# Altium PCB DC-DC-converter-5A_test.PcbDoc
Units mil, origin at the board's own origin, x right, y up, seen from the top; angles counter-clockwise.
Board outline 1075 x 720 mil, 2 copper layers (Top Layer, Bottom Layer); 21 components, 11 nets, 49 pads, 44 vias.
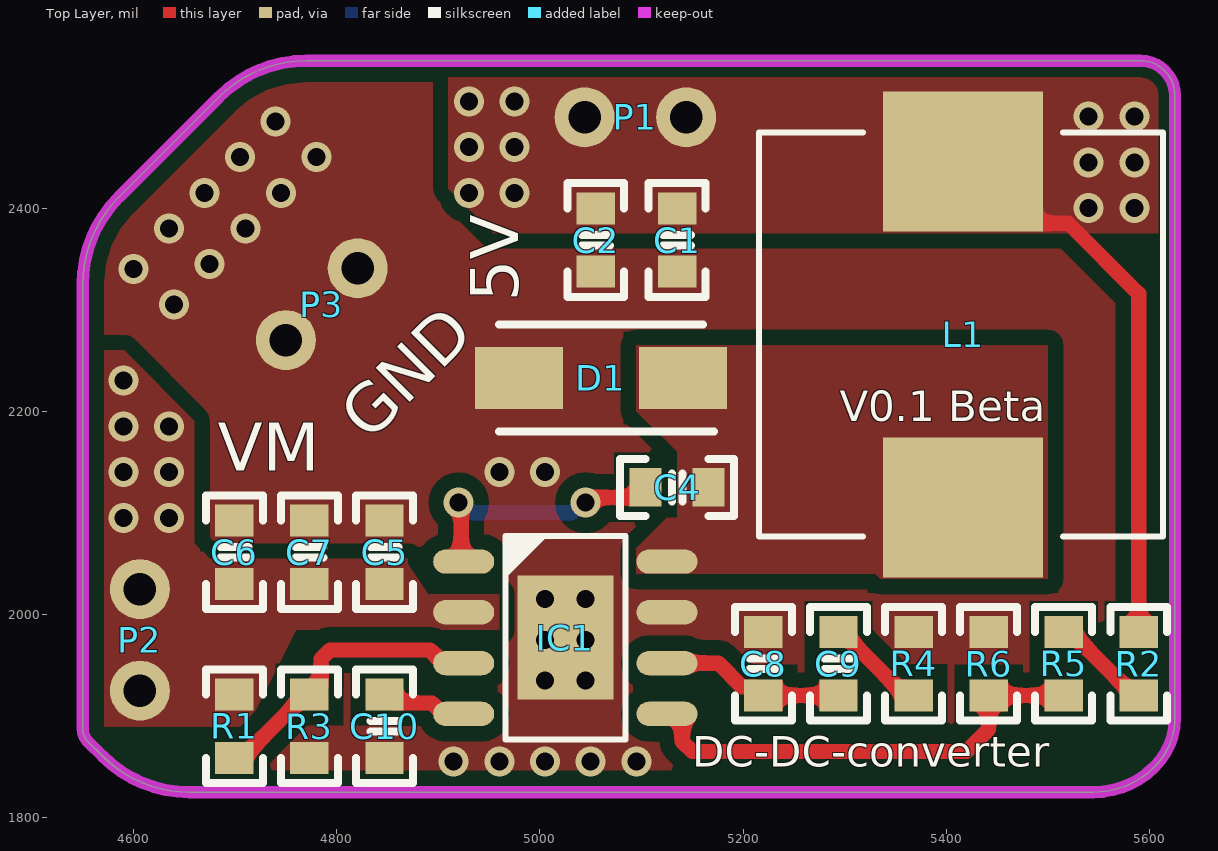
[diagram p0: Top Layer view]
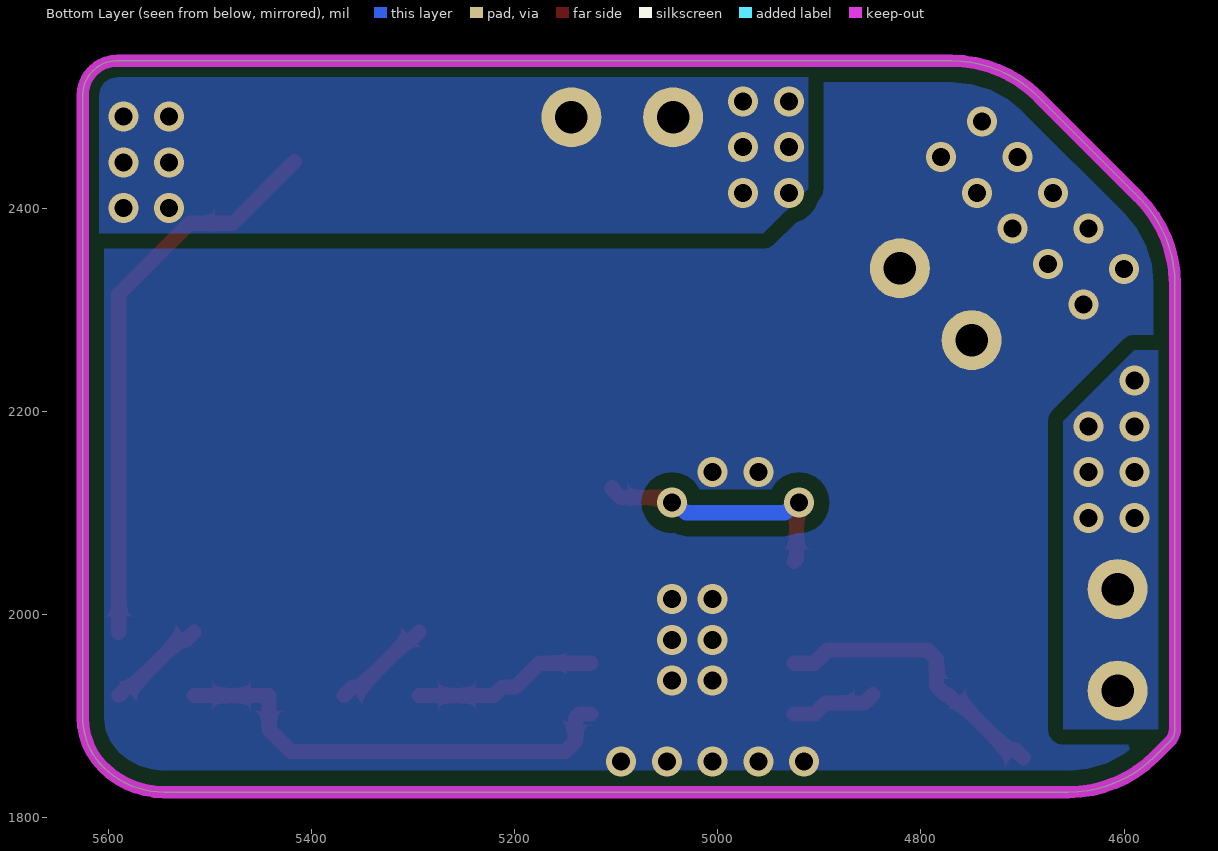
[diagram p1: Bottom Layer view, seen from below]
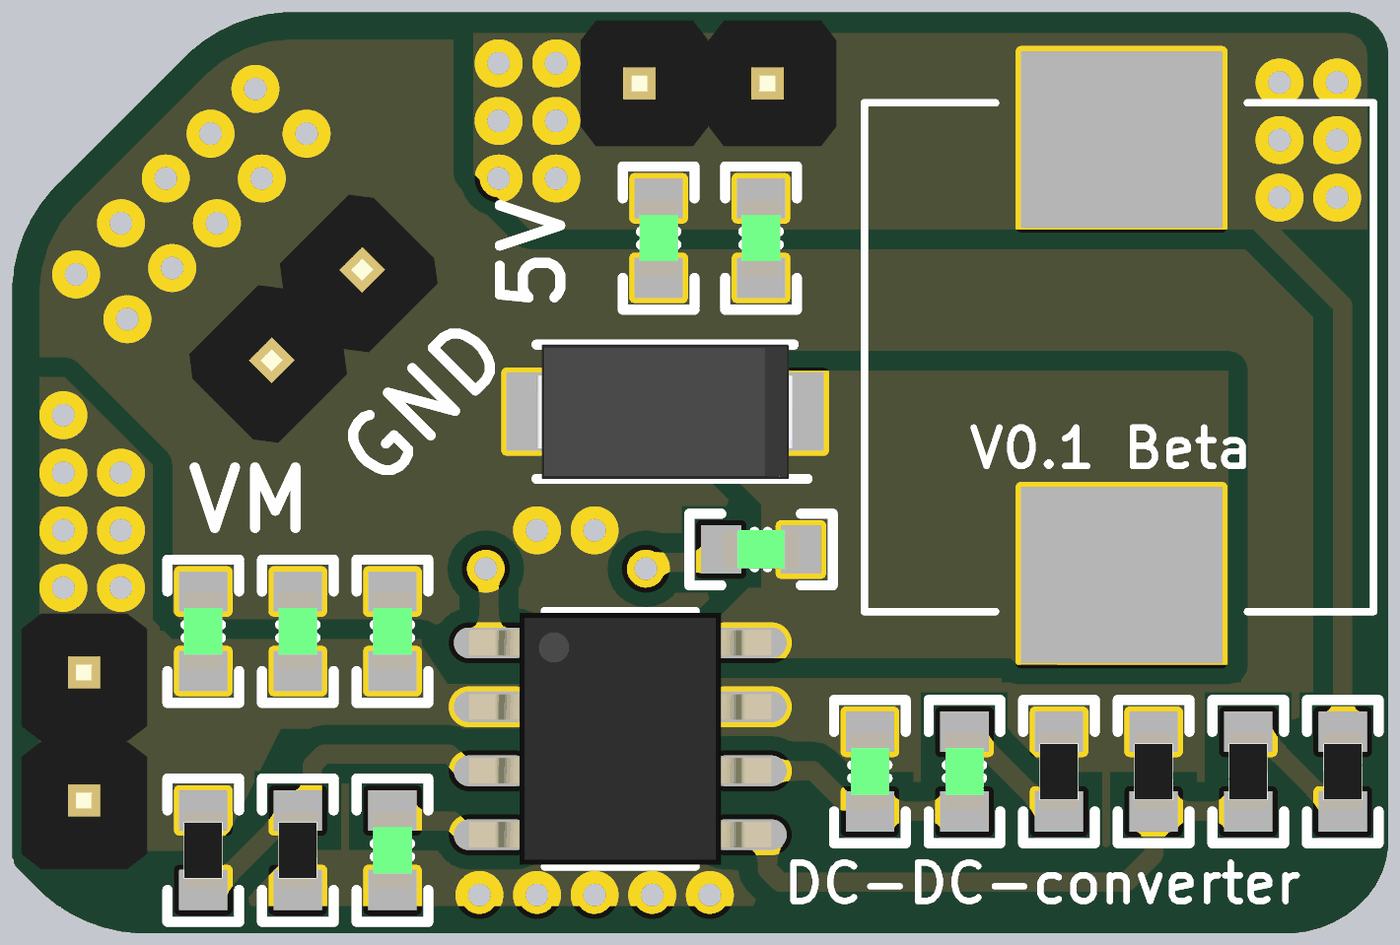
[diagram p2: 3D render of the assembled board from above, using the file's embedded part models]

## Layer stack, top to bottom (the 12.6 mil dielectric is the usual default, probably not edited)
Top Solder: solder mask 0.4, Solder Resist, Dk 3.5
Top Layer: signal copper 1.4
Dielectric 1: dielectric 12.6, FR-4, Dk 4.8
Bottom Layer: signal copper 1.4
Bottom Solder: solder mask 0.4, Solder Resist, Dk 3.5

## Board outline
4555,1875 4569.64,1860.36 ccw(c4655,1945.71) 4655,1825 5544.64,1825 ccw(c5544.64,1910.36) 5605,1850 ccw(c5556.72,1898.28) 5625,1898.28 5625,2510.86 ccw(c5590.86,2510.86) 5615,2535 ccw(c5590.86,2510.86) 5590.86,2545 4770,2545 ccw(c4770,2424.29) 4684.64,2509.64 4585.36,2410.36 ccw(c4670.71,2325) 4550,2325 4550,1887.07 ccw(c4567.07,1887.07)

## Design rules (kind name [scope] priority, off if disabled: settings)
Clearance [All] p1: gap=15 ignorepadtopadclearanceinfootprint=FALSE except(10: Arc-Arc Arc-Track Arc-SMDPad Arc-THPad Arc-Via Arc-Text Arc-Hole Track-Track Track-SMDPad Track-THPad Track-Via Track-Text Track-Hole SMDPad-SMDPad SMDPad-THPad SMDPad-Via SMDPad-Text SMDPad-Hole THPad-THPad THPad-Via THPad-Text THPad-Hole Via-Via Via-Text Via-Hole Text-Text Text-Hole)
PlaneClearance [All] p1: clearance=40
PlaneConnect [All] p1: planeconnectstyle=Direct reliefexpansion=20 reliefentries=4 reliefconductorwidth=10 reliefairgap=10
PolygonConnect [All] p1: connectstyle=Direct reliefconductorwidth=10 reliefentries=4 polygonreliefangle="90 Angle" airgapwidth=10
RoutingVias [All] p1: holewidth=17.72 width=29.53 viastyle="Through Hole" minholewidth=17.72 minwidth=29.53 maxholewidth=17.72 maxwidth=29.53
SolderMaskExpansion [All] p1: expansion=4 istentingtop=FALSE
Width [All] p1: maxlimit=100 minlimit=15 preferedwidth=15
28 further rules are at their usual default settings.

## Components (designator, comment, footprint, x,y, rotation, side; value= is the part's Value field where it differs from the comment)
C1 "47uF" CAP-0603 5135,2368.39 r90 top
C2 "47uF" CAP-0603 5055,2368.39 r90 top
C4 "100nF" CAP-0603 5135,2125 r0 top
C5 "4.7uF" CAP-0603 4847.05,2061.1 r270 top
C6 "4.7uF" CAP-0603 4699.28,2061.1 r270 top
C7 "10nF" CAP-0603 4773.17,2061.1 r270 top
C8 "22pF" CAP-0603 5220,1951.42 r270 top
C9 "2200pF" CAP-0603 5293.88,1951.42 r270 top
C10 "10nF" CAP-0603 4847.05,1890 r90 top
D1 "B340A" DO-214AC_SMA 5060.09,2232.7 r180 top
IC1 "TPS54531DDA" SOIC_8_PAD 5025,1977.05 r270 top
L1 "4.7uH 5A" L-10040 5416.56,2275.31 r90 top
P1 "HDR1x2_2.54" HDR1X2_2.54_180 5043.94,2489.34 r90 top
P2 "HDR1x2_2.54" HDR1X2_2.54_180 4606.34,2025 r0 top
P3 "HDR1x2_2.54" HDR1X2_2.54_180 4820.71,2340.71 r315 top
R1 "665k" R-0603 4699.28,1890 r90 top
R2 "51.1R" R-0603 5589.42,1951.42 r90 top
R3 "130k" R-0603 4773.17,1890 r90 top
R4 "37.4k" R-0603 5367.77,1951.42 r270 top
R5 "10.2k" R-0603 5515.54,1951.42 r90 top
R6 "1.96k" R-0603 5441.65,1951.42 r270 top

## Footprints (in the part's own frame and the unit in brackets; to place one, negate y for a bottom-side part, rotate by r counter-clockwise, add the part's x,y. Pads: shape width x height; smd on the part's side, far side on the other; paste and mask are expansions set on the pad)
CAP-0603 [mm]
  rect 0.8x0.96 smd: 1(-0.79,0) 2(0.79,0)
  silkscreen extent -1.42,-0.71 1.42,0.71, body extent -0.76,-0.39 0.76,0.39, height 0.9
DO-214AC_SMA [mm]
  rect 2.2x1.55 smd: 1(2.05,0) 2(-2.05,0)
  silkscreen extent -2.83,-1.33 2.55,1.33, body extent -2.55,-1.33 2.55,1.33, height 2.29
HDR1X2_2.54_180 [mm]
  round 1.5 hole 0.813: 1(0,0) 2(0,-2.54)
  body extent -1.25,-3.81 1.25,1.27, height 8.2
L-10040 [mm] "10.1*11.6*4.0MM(长*宽*高)"
  rect 3.5x4 smd: 1(-4.326,0) 2(4.326,0)
  silkscreen extent -5.05,-5 5.05,5.1, body extent -5,-5 5,5.08, height 4
R-0603 [mm]
  rect 0.8x0.96 smd: 1(-0.79,0) 2(0.79,0)
  silkscreen extent -1.42,-0.71 1.42,0.71, body extent -0.76,-0.38 0.76,0.38, height 0.41
SOIC_8_PAD [mil]
  oval 24x60 smd: 1(-75,-100) 2(-25,-100) 3(25,-100) 4(75,-100) 5(75,100) 6(25,100) 7(-25,100) 8(-75,100)
  rect 122.05x94.49 smd: 9(0,0)
  silkscreen extent -100,-59 100,59, body extent -98,-118 98,118, height 71

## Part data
C1 C2 C4 C5 C6 C7 C8 C9 C10: library part CAP, "贴片电容", Package=0402, SuppliersPartNumber=C52923
D1: library part DIODE, "肖特基二极管", Package=SMA(DO-214AC), SuppliersPartNumber=C22452
IC1: "集成稳压芯片", Manufacturer_Name="Texas Instruments", Mouser Part Number=595-TPS54531DDA
L1: library part INDUCTOR, "电感", Package=0402, SuppliersPartNumber=C32041
P1 P2 P3: "Header"
R1 R2 R3 R4 R5 R6: library part RES, "贴片电阻", Package=0805, SuppliersPartNumber=C17798

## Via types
v1: diameter 29.53, hole 17.72, Top Layer to Bottom Layer, 44 vias

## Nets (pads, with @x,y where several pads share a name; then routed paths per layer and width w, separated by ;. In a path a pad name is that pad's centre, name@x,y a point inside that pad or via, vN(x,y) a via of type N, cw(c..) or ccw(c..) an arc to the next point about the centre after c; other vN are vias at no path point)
5V: C1.2 C2.2 L1.2 P1.1 P1.2 R2.2 | length 559.8
  Top Layer w15: L1.2 5477.19,2385 5520,2385 5589.42,2315.58 R2.2
  other v1: 5540,2400 5585,2400 4930,2415 4975,2415 5540,2445 5585,2445 4930,2460 4975,2460 5540,2490 5585,2490 4930,2505 4975,2505
GND: C1.1 C2.1 C5.1 C6.1 C7.1 C8.1 C10.1 D1.1 IC1.7 IC1.9 P3.1 P3.2 R3.1 R4.1 R6.1
  other v1: 4915,1855 4960,1855 5005,1855 5050,1855 5095,1855 5005,1935 5045,1935 5005,1975 5045,1975 5005,2015 5045,2015 4960,2140 5005,2140 4640,2305 4600,2340 4675,2345 4635,2380 4710,2380 4670,2415 4745,2415 4705,2450 4780,2450 4740,2485
NetC4_1: C4.1 IC1.1 | length 259.4
  Top Layer w15: v1(4920,2110) 4922.5,2107.5 4922.5,2054.55 IC1.1 ; v1(5045,2110) 5048.93,2110 5053.93,2115 5095.65,2115 5103.9,2123.25 C4.1
  Bottom Layer w15: v1(4920,2110) 4923.93,2110 4933.93,2100 5031.07,2100 5041.07,2110 v1(5045,2110)
NetC4_2: C4.2 D1.2 IC1.8 L1.1
NetC8_2: C8.2 C9.2 IC1.6 | length 182
  Top Layer w15: IC1.6 5175.6,1952.05 5199.1,1928.56 5211.75,1928.56 C8.2 C9.2
NetC9_1: C9.1 R4.2 | length 99.7
  Top Layer w15: C9.1 5302.13,1974.27 5305.73,1974.27 5351.44,1928.56 5359.52,1928.56 R4.2
NetC10_2: C10.2 IC1.4 | length 85.8
  Top Layer w15: C10.2 4855.3,1912.85 4893.76,1912.85 4904.56,1902.05 IC1.4
NetIC1_3: IC1.3 R1.1 R3.2 | length 290.8
  Top Layer w15: R1.1 4707.53,1867.15 4715.15,1867.15 4760.85,1912.85 4764.92,1912.85 R3.2 4776.32,1921.1 4784.57,1929.35 4784.57,1956.21 4793.35,1965 4891.62,1965 4904.56,1952.05 IC1.3
NetIC1_5: IC1.5 R5.1 R6.2 | length 461.9
  Top Layer w15: IC1.5 5135.84,1902.05 5140,1897.9 5140,1875 5150,1865 5420,1865 5441.65,1886.65 R6.2 R5.1
NetR2_1: R2.1 R5.2 | length 99.7
  Top Layer w15: R5.2 5523.78,1974.27 5530.73,1974.27 5576.44,1928.56 5581.17,1928.56 R2.1
VM: C5.2 C6.2 C7.2 IC1.2 P2.1 P2.2 R1.2
  other v1: 4590,2095 4635,2095 4590,2140 4635,2140 4590,2185 4635,2185 4590,2230

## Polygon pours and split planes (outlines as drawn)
GND on Top Layer "GND_L01_P007" (solid, remove dead copper, pour order 7): 4413.42,2621.77 4413.42,1596.77 5823.42,1596.77 5823.42,2621.77
5V on Top Layer "5V_L01_P003" (solid, remove dead copper, pour order 3): 4910,2545 4910,2419.14 4954.14,2375 5625,2375 5625,2545 5182.93,2545
VM on Top Layer "VM_L01_P002" (solid, pour order 2): 4660,2070 4675,2055 4660,2055
VM on Top Layer "VM_L01_P001" (solid, remove dead copper, pour order 1): 4550,2260 4590.86,2260 4660,2190.86 4660,2055 4870,2055 4870,2050 4890,2020 4960,2020 4960,1985 4760,1985 4720,1905 4704.81,1889.47 4550,1889.47
NetC4_2 on Top Layer "NETC4_2_L01_P000" (solid, pour order 0): 5095,2040 5330,2040 5335,2035 5500,2035 5500,2265 5095,2265 5095,2200 5135,2160 5135,2095 5125,2095 5095,2065
GND on Bottom Layer "GND_L02_P006" (solid, remove dead copper, pour order 6): 4440,2595 4440,1650 5795,1650 5795,2595
VM on Bottom Layer "VM_L02_P005" (solid, pour order 5): 4660,1887.07 4660,2190 4590,2260 4565,2260 4565,1887.07
5V on Bottom Layer "5V_L02_P004" (solid, remove dead copper, pour order 4): 4910.86,2545 4910.86,2419.14 4955,2375 5625.86,2375 5625.86,2545 5183.79,2545

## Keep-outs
Keep-Out Layer:
  lines w12: 4550,1887.07 ccw(c4567.07,1887.07) 4555,1875 4569.64,1860.36 ccw(c4655,1945.71) 4655,1825 4880,1825 5070.5,1825 5085.5,1825 5505,1825 5544.64,1825 ccw(c5544.64,1910.36) 5605,1850 ccw(c5556.72,1898.28) 5625,1898.28 5625,1902.07 5625,2507.93 5625,2510.86 ccw(c5590.86,2510.86) 5615,2535 ccw(c5590.86,2510.86) 5590.86,2545 5182.93,2545 4890,2545 4770,2545 ccw(c4770,2424.29) 4684.64,2509.64 4585.36,2410.36 ccw(c4670.71,2325) 4550,2325 4550,2065 4550,1887.07

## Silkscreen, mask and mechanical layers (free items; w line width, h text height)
Top Overlay:
  text "5V" at 4978.61,2307.87 h47.24 r90
  text "V0.1 Beta" at 5295,2190 h30
  text "GND" at 4832.27,2168.87 h47.24 r45
  text "VM" at 4682.87,2141.39 h47.24
  text "DC-DC-converter" at 5150,1850 h30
